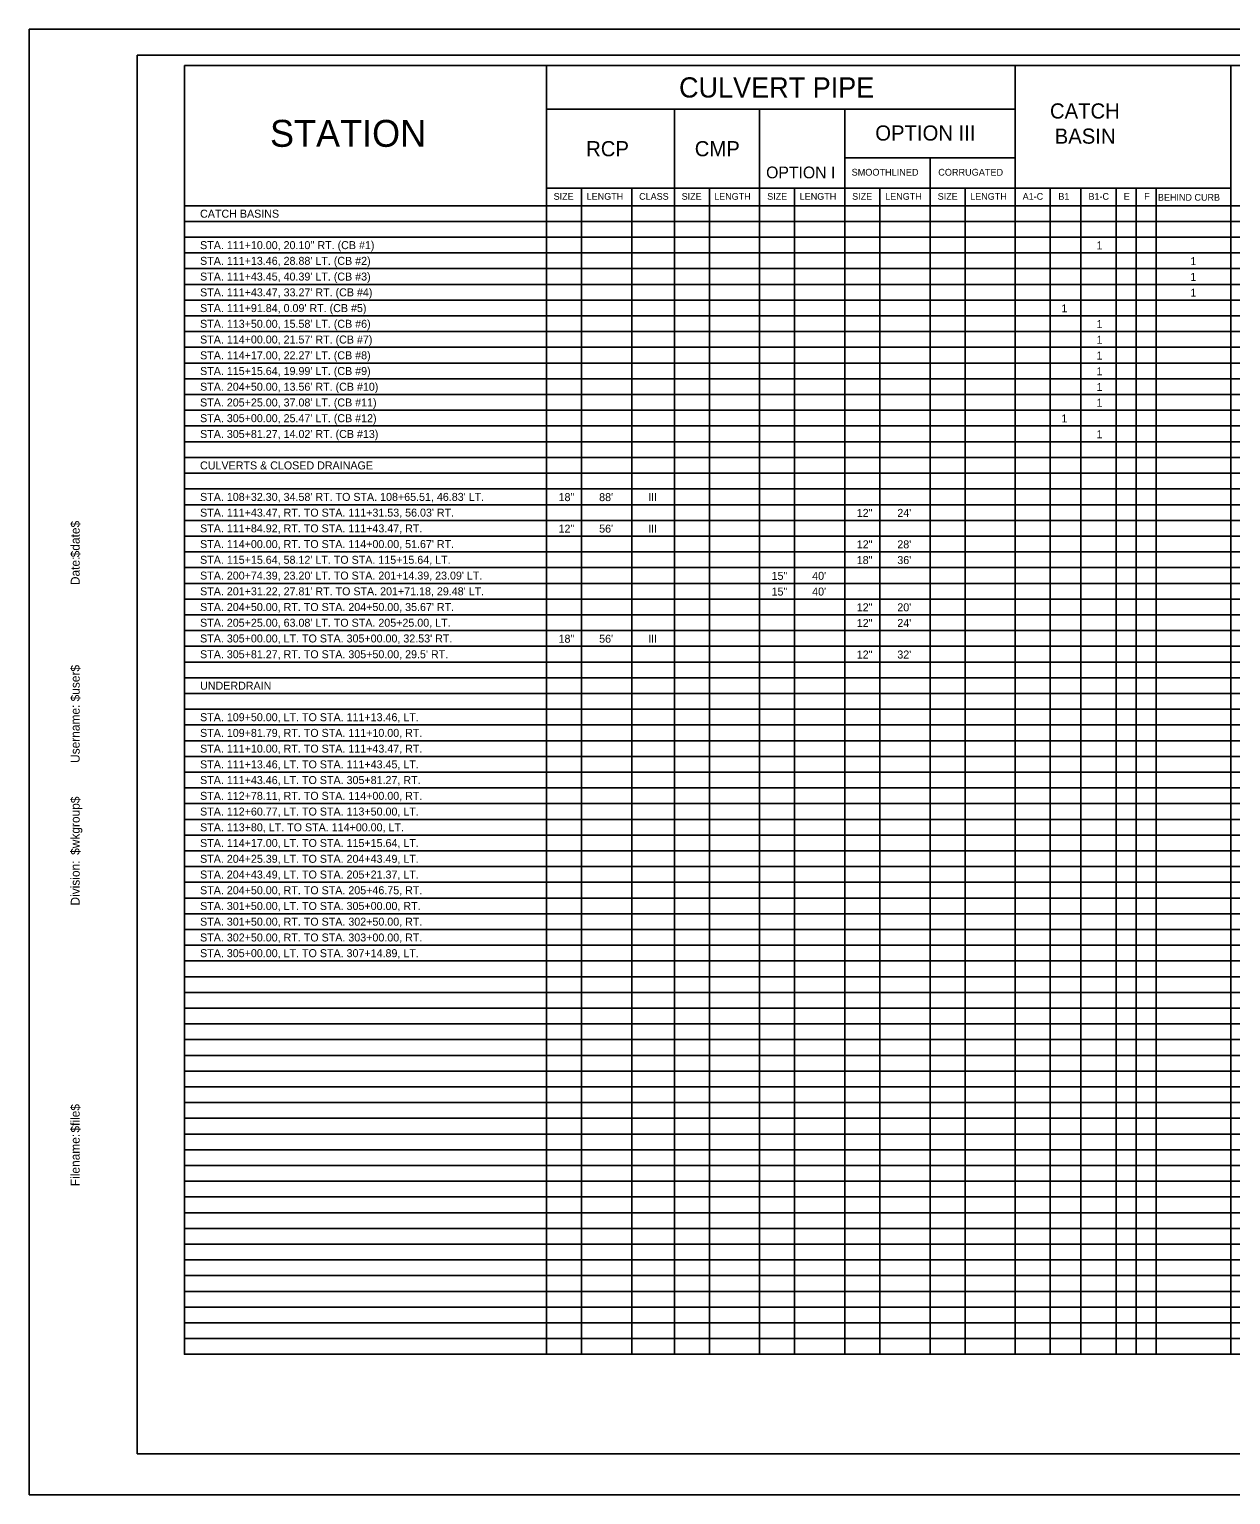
# Model space of a CAD drawing. Extents: x 2075518.1 to 2075585.6, y 1172412.5 to 1172434.5.
# Drawn here: x 2075518.14 to 2075536.17, y 1172412.49 to 1172434.49 of the extents above; entities that cross this region are included whole.
import ezdxf

# ---------------------------------------------------------------- set-up
doc = ezdxf.new("R2010")
doc.units = 0
for name, color, linetype in [('ANNOTATION', 7, 'Continuous'), ('Border', 7, 'Continuous'), ('PLOT BOUNDARY', 7, 'Continuous')]:
    doc.layers.add(name, color=color, linetype=linetype)

msp = doc.modelspace()

# ---------------------------------------------------------------- linework, layer by layer
at = {"layer": 'Border'}
for p, q in [((2075551.755, 1172434.098), (2075519.755, 1172434.098)), ((2075519.755, 1172434.098), (2075519.755, 1172413.098)), ((2075525.899, 1172433.288), (2075525.899, 1172433.945)), ((2075532.933, 1172433.288), (2075532.933, 1172433.945)), ((2075536.166, 1172433.288), (2075536.166, 1172433.945)), ((2075525.899, 1172432.555), (2075525.899, 1172433.288)), ((2075525.899, 1172433.288), (2075526.425, 1172433.288)), ((2075526.425, 1172433.288), (2075527.178, 1172433.288)), ((2075527.178, 1172433.288), (2075527.817, 1172433.288)), ((2075527.817, 1172432.555), (2075527.817, 1172433.288)), ((2075527.817, 1172433.288), (2075528.344, 1172433.288)), ((2075528.344, 1172433.288), (2075529.096, 1172433.288)), ((2075529.096, 1172432.555), (2075529.096, 1172433.288)), ((2075529.096, 1172433.288), (2075529.622, 1172433.288)), ((2075529.622, 1172433.288), (2075530.901, 1172433.288)), ((2075530.375, 1172432.102), (2075530.375, 1172433.288)), ((2075530.901, 1172433.288), (2075532.933, 1172433.288)), ((2075532.933, 1172432.555), (2075532.933, 1172433.288)), ((2075536.166, 1172432.555), (2075536.166, 1172433.288)), ((2075525.899, 1172432.102), (2075525.899, 1172432.555)), ((2075527.817, 1172432.102), (2075527.817, 1172432.555)), ((2075529.096, 1172432.102), (2075529.096, 1172432.555)), ((2075530.375, 1172432.555), (2075530.901, 1172432.555)), ((2075530.901, 1172432.555), (2075532.18, 1172432.555)), ((2075531.654, 1172431.838), (2075531.654, 1172432.555)), ((2075532.18, 1172432.555), (2075532.933, 1172432.555)), ((2075532.933, 1172432.102), (2075532.933, 1172432.555)), ((2075536.166, 1172432.102), (2075536.166, 1172432.555)), ((2075525.899, 1172431.838), (2075525.899, 1172432.102)), ((2075525.899, 1172432.102), (2075526.425, 1172432.102)), ((2075526.425, 1172431.838), (2075526.425, 1172432.102)), ((2075526.425, 1172432.102), (2075527.178, 1172432.102)), ((2075527.178, 1172431.838), (2075527.178, 1172432.102)), ((2075527.178, 1172432.102), (2075527.817, 1172432.102)), ((2075527.817, 1172431.838), (2075527.817, 1172432.102)), ((2075527.817, 1172432.102), (2075528.344, 1172432.102)), ((2075528.344, 1172431.838), (2075528.344, 1172432.102)), ((2075528.344, 1172432.102), (2075529.096, 1172432.102)), ((2075529.096, 1172431.838), (2075529.096, 1172432.102)), ((2075529.096, 1172432.102), (2075529.622, 1172432.102)), ((2075529.622, 1172431.838), (2075529.622, 1172432.102)), ((2075529.622, 1172432.102), (2075530.375, 1172432.102)), ((2075530.375, 1172431.838), (2075530.375, 1172432.102)), ((2075530.375, 1172432.102), (2075530.901, 1172432.102)), ((2075530.901, 1172431.838), (2075530.901, 1172432.102)), ((2075530.901, 1172432.102), (2075531.654, 1172432.102)), ((2075531.654, 1172432.102), (2075532.18, 1172432.102)), ((2075532.18, 1172431.838), (2075532.18, 1172432.102)), ((2075532.18, 1172432.102), (2075532.933, 1172432.102)), ((2075532.933, 1172431.838), (2075532.933, 1172432.102)), ((2075532.933, 1172432.102), (2075533.459, 1172432.102)), ((2075533.459, 1172431.838), (2075533.459, 1172432.102)), ((2075533.459, 1172432.102), (2075533.985, 1172432.102)), ((2075533.919, 1172431.838), (2075533.919, 1172432.102)), ((2075533.985, 1172432.102), (2075534.512, 1172432.102)), ((2075534.446, 1172431.838), (2075534.446, 1172432.102)), ((2075534.512, 1172432.102), (2075534.812, 1172432.102)), ((2075534.746, 1172431.838), (2075534.746, 1172432.102)), ((2075534.812, 1172432.102), (2075536.166, 1172432.102)), ((2075535.047, 1172431.838), (2075535.047, 1172432.102)), ((2075536.166, 1172431.838), (2075536.166, 1172432.102)), ((2075525.899, 1172431.838), (2075525.899, 1172414.594)), ((2075526.425, 1172431.838), (2075526.425, 1172414.594)), ((2075527.178, 1172431.838), (2075527.178, 1172414.594)), ((2075527.817, 1172431.838), (2075527.817, 1172414.594)), ((2075528.344, 1172431.838), (2075528.344, 1172414.594)), ((2075529.096, 1172431.838), (2075529.096, 1172414.594)), ((2075529.622, 1172431.838), (2075529.622, 1172414.594)), ((2075530.375, 1172431.838), (2075530.375, 1172414.594)), ((2075530.901, 1172431.838), (2075530.901, 1172414.594)), ((2075531.654, 1172431.838), (2075531.654, 1172414.594)), ((2075532.18, 1172431.838), (2075532.18, 1172414.594)), ((2075532.933, 1172431.838), (2075532.933, 1172414.594)), ((2075533.459, 1172431.838), (2075533.459, 1172414.594)), ((2075533.919, 1172431.838), (2075533.919, 1172414.594)), ((2075534.446, 1172431.838), (2075534.446, 1172414.594)), ((2075534.746, 1172431.838), (2075534.746, 1172414.594)), ((2075535.047, 1172431.838), (2075535.047, 1172414.594)), ((2075536.166, 1172431.838), (2075536.166, 1172414.594)), ((2075520.465, 1172431.601), (2075549.256, 1172431.601)), ((2075520.465, 1172431.365), (2075549.256, 1172431.365)), ((2075520.465, 1172431.129), (2075549.256, 1172431.129)), ((2075520.465, 1172430.893), (2075549.256, 1172430.893)), ((2075520.465, 1172430.657), (2075549.256, 1172430.657)), ((2075520.465, 1172430.42), (2075549.256, 1172430.42)), ((2075520.465, 1172430.184), (2075549.256, 1172430.184)), ((2075520.465, 1172429.948), (2075549.256, 1172429.948)), ((2075520.465, 1172429.712), (2075549.256, 1172429.712)), ((2075520.465, 1172429.475), (2075549.256, 1172429.475)), ((2075520.465, 1172429.239), (2075549.256, 1172429.239)), ((2075520.465, 1172429.003), (2075549.256, 1172429.003)), ((2075520.465, 1172428.767), (2075549.256, 1172428.767)), ((2075520.465, 1172428.531), (2075549.256, 1172428.531)), ((2075520.465, 1172428.294), (2075549.256, 1172428.294)), ((2075520.465, 1172428.058), (2075549.256, 1172428.058)), ((2075520.465, 1172427.822), (2075549.256, 1172427.822)), ((2075520.465, 1172427.586), (2075549.256, 1172427.586)), ((2075520.465, 1172427.349), (2075549.256, 1172427.349)), ((2075520.465, 1172427.113), (2075549.256, 1172427.113)), ((2075520.465, 1172426.877), (2075549.256, 1172426.877)), ((2075520.465, 1172426.641), (2075549.256, 1172426.641)), ((2075520.465, 1172426.405), (2075549.256, 1172426.405)), ((2075520.465, 1172426.168), (2075549.256, 1172426.168)), ((2075520.465, 1172425.932), (2075549.256, 1172425.932)), ((2075520.465, 1172425.696), (2075549.256, 1172425.696)), ((2075520.465, 1172425.46), (2075549.256, 1172425.46)), ((2075520.465, 1172425.224), (2075549.256, 1172425.224)), ((2075520.465, 1172424.987), (2075549.256, 1172424.987)), ((2075520.465, 1172424.751), (2075549.256, 1172424.751)), ((2075520.465, 1172424.515), (2075549.256, 1172424.515)), ((2075520.465, 1172424.279), (2075549.256, 1172424.279)), ((2075520.465, 1172424.042), (2075549.256, 1172424.042)), ((2075520.465, 1172423.806), (2075549.256, 1172423.806)), ((2075520.465, 1172423.57), (2075549.256, 1172423.57)), ((2075520.465, 1172423.334), (2075549.256, 1172423.334)), ((2075520.465, 1172423.098), (2075549.256, 1172423.098)), ((2075520.465, 1172422.861), (2075549.256, 1172422.861)), ((2075520.465, 1172422.625), (2075549.256, 1172422.625)), ((2075520.465, 1172422.389), (2075549.256, 1172422.389)), ((2075520.465, 1172422.153), (2075549.256, 1172422.153)), ((2075520.465, 1172421.916), (2075549.256, 1172421.916)), ((2075520.465, 1172421.68), (2075549.256, 1172421.68)), ((2075520.465, 1172421.444), (2075549.256, 1172421.444)), ((2075520.465, 1172421.208), (2075549.256, 1172421.208)), ((2075520.465, 1172420.972), (2075549.256, 1172420.972)), ((2075520.465, 1172420.735), (2075549.256, 1172420.735)), ((2075520.465, 1172420.499), (2075549.256, 1172420.499)), ((2075520.465, 1172420.263), (2075549.256, 1172420.263)), ((2075520.465, 1172420.027), (2075549.256, 1172420.027)), ((2075520.465, 1172419.79), (2075549.256, 1172419.79)), ((2075520.465, 1172419.554), (2075549.256, 1172419.554)), ((2075520.465, 1172419.318), (2075549.256, 1172419.318)), ((2075520.465, 1172419.082), (2075549.256, 1172419.082)), ((2075520.465, 1172418.846), (2075549.256, 1172418.846)), ((2075520.465, 1172418.609), (2075549.256, 1172418.609)), ((2075520.465, 1172418.373), (2075549.256, 1172418.373)), ((2075520.465, 1172418.137), (2075549.256, 1172418.137)), ((2075520.465, 1172417.901), (2075549.256, 1172417.901)), ((2075520.465, 1172417.664), (2075549.256, 1172417.664)), ((2075520.465, 1172417.428), (2075549.256, 1172417.428)), ((2075520.465, 1172417.192), (2075549.256, 1172417.192)), ((2075520.465, 1172416.956), (2075549.256, 1172416.956)), ((2075520.465, 1172416.72), (2075549.256, 1172416.72)), ((2075520.465, 1172416.483), (2075549.256, 1172416.483)), ((2075520.465, 1172416.247), (2075549.256, 1172416.247)), ((2075520.465, 1172416.011), (2075549.256, 1172416.011)), ((2075520.465, 1172415.775), (2075549.256, 1172415.775)), ((2075520.465, 1172415.538), (2075549.256, 1172415.538)), ((2075520.465, 1172415.302), (2075549.256, 1172415.302)), ((2075520.465, 1172415.066), (2075549.256, 1172415.066)), ((2075520.465, 1172414.83), (2075549.256, 1172414.83)), ((2075521.307, 1172414.594), (2075548.203, 1172414.594)), ((2075519.755, 1172413.098), (2075551.755, 1172413.098))]:
    msp.add_line(p, q, dxfattribs=at)
msp.add_lwpolyline([(2075520.465, 1172433.945), (2075549.256, 1172433.945), (2075549.256, 1172431.838), (2075520.465, 1172431.838)], close=True, dxfattribs=at)
msp.add_lwpolyline([(2075520.465, 1172431.838), (2075520.465, 1172414.594), (2075549.256, 1172414.594), (2075549.256, 1172431.838)], dxfattribs=at)
at = {"layer": 'PLOT BOUNDARY'}
msp.add_lwpolyline([(2075518.136, 1172412.486), (2075552.136, 1172412.486), (2075552.136, 1172434.486), (2075518.136, 1172434.486)], close=True, dxfattribs=at)

# ---------------------------------------------------------------- texts
at = {"layer": 'ANNOTATION'}
for s, p in [('CATCH BASINS', (2075520.699, 1172431.658)), ("STA. 111+10.00, 20.10'' RT. (CB #1)", (2075520.699, 1172431.186)), ('1', (2075534.152, 1172431.182)), ("STA. 111+13.46, 28.88' LT. (CB #2)", (2075520.699, 1172430.95)), ('1', (2075535.561, 1172430.946)), ("STA. 111+43.45, 40.39' LT. (CB #3)", (2075520.699, 1172430.714)), ('1', (2075535.561, 1172430.71)), ("STA. 111+43.47, 33.27' RT. (CB #4)", (2075520.699, 1172430.477)), ('1', (2075535.561, 1172430.473)), ("STA. 111+91.84, 0.09' RT. (CB #5)", (2075520.699, 1172430.241)), ('1', (2075533.626, 1172430.237)), ("STA. 113+50.00, 15.58' LT. (CB #6)", (2075520.699, 1172430.005)), ('1', (2075534.152, 1172430.001)), ("STA. 114+00.00, 21.57' RT. (CB #7)", (2075520.699, 1172429.769)), ('1', (2075534.152, 1172429.765)), ("STA. 114+17.00, 22.27' LT. (CB #8)", (2075520.699, 1172429.532)), ('1', (2075534.152, 1172429.529)), ("STA. 115+15.64, 19.99' LT. (CB #9)", (2075520.699, 1172429.296)), ('1', (2075534.152, 1172429.292)), ("STA. 204+50.00, 13.56' RT. (CB #10)", (2075520.699, 1172429.06)), ('1', (2075534.152, 1172429.056)), ("STA. 205+25.00, 37.08' LT. (CB #11)", (2075520.699, 1172428.824)), ('1', (2075534.152, 1172428.82)), ("STA. 305+00.00, 25.47' LT. (CB #12)", (2075520.699, 1172428.588)), ('1', (2075533.626, 1172428.584)), ("STA. 305+81.27, 14.02' RT. (CB #13)", (2075520.699, 1172428.351)), ('1', (2075534.152, 1172428.347)), ('CULVERTS & CLOSED DRAINAGE', (2075520.699, 1172427.879)), ("STA. 108+32.30, 34.58' RT. TO STA. 108+65.51, 46.83' LT.", (2075520.699, 1172427.406)), ('18"', (2075526.079, 1172427.403)), ("88'", (2075526.688, 1172427.403)), ('III', (2075527.424, 1172427.403)), ("STA. 111+43.47, RT. TO STA. 111+31.53, 56.03' RT.", (2075520.699, 1172427.17)), ('12"', (2075530.554, 1172427.166)), ("24'", (2075531.163, 1172427.166)), ('STA. 111+84.92, RT. TO STA. 111+43.47, RT.', (2075520.699, 1172426.934)), ('12"', (2075526.079, 1172426.93)), ("56'", (2075526.688, 1172426.93)), ('III', (2075527.424, 1172426.93)), ("STA. 114+00.00, RT. TO STA. 114+00.00, 51.67' RT.", (2075520.699, 1172426.698)), ('12"', (2075530.554, 1172426.694)), ("28'", (2075531.163, 1172426.694)), ("STA. 115+15.64, 58.12' LT. TO STA. 115+15.64, LT.", (2075520.699, 1172426.462)), ('18"', (2075530.554, 1172426.458)), ("36'", (2075531.163, 1172426.458)), ("STA. 200+74.39, 23.20' LT. TO STA. 201+14.39, 23.09' LT.", (2075520.699, 1172426.225)), ('15"', (2075529.276, 1172426.221)), ("40'", (2075529.885, 1172426.221)), ("STA. 201+31.22, 27.81' RT. TO STA. 201+71.18, 29.48' LT.", (2075520.699, 1172425.989)), ('15"', (2075529.276, 1172425.985)), ("40'", (2075529.885, 1172425.985)), ("STA. 204+50.00, RT. TO STA. 204+50.00, 35.67' RT.", (2075520.699, 1172425.753)), ('12"', (2075530.554, 1172425.749)), ("20'", (2075531.163, 1172425.749)), ("STA. 205+25.00, 63.08' LT. TO STA. 205+25.00, LT.", (2075520.699, 1172425.517)), ('12"', (2075530.554, 1172425.513)), ("24'", (2075531.163, 1172425.513)), ("STA. 305+00.00, LT. TO STA. 305+00.00, 32.53' RT.", (2075520.699, 1172425.281)), ('18"', (2075526.079, 1172425.277)), ("56'", (2075526.688, 1172425.277)), ('III', (2075527.424, 1172425.277)), ("STA. 305+81.27, RT. TO STA. 305+50.00, 29.5' RT.", (2075520.699, 1172425.044)), ('12"', (2075530.554, 1172425.04)), ("32'", (2075531.163, 1172425.04)), ('UNDERDRAIN', (2075520.699, 1172424.572)), ('STA. 109+50.00, LT. TO STA. 111+13.46, LT.', (2075520.699, 1172424.099)), ('STA. 109+81.79, RT. TO STA. 111+10.00, RT.', (2075520.699, 1172423.863)), ('STA. 111+10.00, RT. TO STA. 111+43.47, RT.', (2075520.699, 1172423.627)), ('STA. 111+13.46, LT. TO STA. 111+43.45, LT.', (2075520.699, 1172423.391)), ('STA. 111+43.46, LT. TO STA. 305+81.27, RT.', (2075520.699, 1172423.155)), ('STA. 112+78.11, RT. TO STA. 114+00.00, RT.', (2075520.699, 1172422.918)), ('STA. 112+60.77, LT. TO STA. 113+50.00, LT.', (2075520.699, 1172422.682)), ('STA. 113+80, LT. TO STA. 114+00.00, LT.', (2075520.699, 1172422.446)), ('STA. 114+17.00, LT. TO STA. 115+15.64, LT.', (2075520.699, 1172422.21)), ('STA. 204+25.39, LT. TO STA. 204+43.49, LT.', (2075520.699, 1172421.973)), ('STA. 204+43.49, LT. TO STA. 205+21.37, LT.', (2075520.699, 1172421.737)), ('STA. 204+50.00, RT. TO STA. 205+46.75, RT.', (2075520.699, 1172421.501)), ('STA. 301+50.00, LT. TO STA. 305+00.00, RT.', (2075520.699, 1172421.265)), ('STA. 301+50.00, RT. TO STA. 302+50.00, RT.', (2075520.699, 1172421.029)), ('STA. 302+50.00, RT. TO STA. 303+00.00, RT.', (2075520.699, 1172420.792)), ('STA. 305+00.00, LT. TO STA. 307+14.89, LT.', (2075520.699, 1172420.556))]:
    msp.add_text(s, height=0.12, dxfattribs=at).set_placement(p)
at = {"layer": 'Border'}
for s, height, p in [('CULVERT PIPE', 0.30331, (2075527.887, 1172433.462)), ('CATCH', 0.2275, (2075533.454, 1172433.147)), ('STATION', 0.4044, (2075521.748, 1172432.722)), ('OPTION III', 0.2275, (2075530.832, 1172432.816)), ('BASIN', 0.2275, (2075533.525, 1172432.769)), ('RCP', 0.2275, (2075526.493, 1172432.58)), ('CMP', 0.2275, (2075528.123, 1172432.58)), ('OPTION I', 0.1769, (2075529.194, 1172432.249)), ('SMOOTHLINED', 0.10238, (2075530.477, 1172432.289)), ('CORRUGATED', 0.1024, (2075531.777, 1172432.289)), ('SIZE', 0.1011, (2075526.005, 1172431.927)), ('LENGTH', 0.1011, (2075526.501, 1172431.927)), ('CLASS', 0.1011, (2075527.288, 1172431.927)), ('SIZE', 0.1011, (2075527.926, 1172431.927)), ('LENGTH', 0.1011, (2075528.414, 1172431.927)), ('SIZE', 0.1011, (2075529.21, 1172431.927)), ('LENGTH', 0.1011, (2075529.698, 1172431.927)), ('SIZE', 0.1011, (2075530.485, 1172431.927)), ('LENGTH', 0.1011, (2075530.981, 1172431.927)), ('SIZE', 0.1011, (2075531.769, 1172431.927)), ('LENGTH', 0.1011, (2075532.257, 1172431.927)), ('A1-C', 0.1011, (2075533.044, 1172431.927)), ('B1', 0.1011, (2075533.58, 1172431.927)), ('B1-C', 0.1011, (2075534.032, 1172431.927)), ('E', 0.101, (2075534.561, 1172431.927)), ('F', 0.101, (2075534.868, 1172431.927)), ('BEHIND CURB', 0.1011, (2075535.074, 1172431.913))]:
    msp.add_text(s, height=height, dxfattribs=at).set_placement(p)
for s, p in [('$date$', (2075518.892, 1172426.559)), ('Date:', (2075518.892, 1172426.142)), ('$user$', (2075518.892, 1172424.396)), ('Username:', (2075518.892, 1172423.472)), ('$wkgroup$', (2075518.892, 1172422.092)), ('Division:', (2075518.892, 1172421.331)), ('$file$', (2075518.892, 1172417.923)), ('Filename:', (2075518.892, 1172417.118))]:
    msp.add_text(s, height=0.1339, rotation=90, dxfattribs=at).set_placement(p)

doc.saveas('drawing.dxf')
